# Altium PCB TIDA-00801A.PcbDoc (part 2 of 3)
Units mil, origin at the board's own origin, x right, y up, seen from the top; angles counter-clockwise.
Board outline 5000 x 3000 mil, 6 copper layers (Top Layer, Signal Layer 1, Signal Layer 2, Signal Layer 3, Signal Layer 4, Bottom Layer), stack 60.502 mil thick; 195 components, 95 nets, 602 pads, 757 vias.
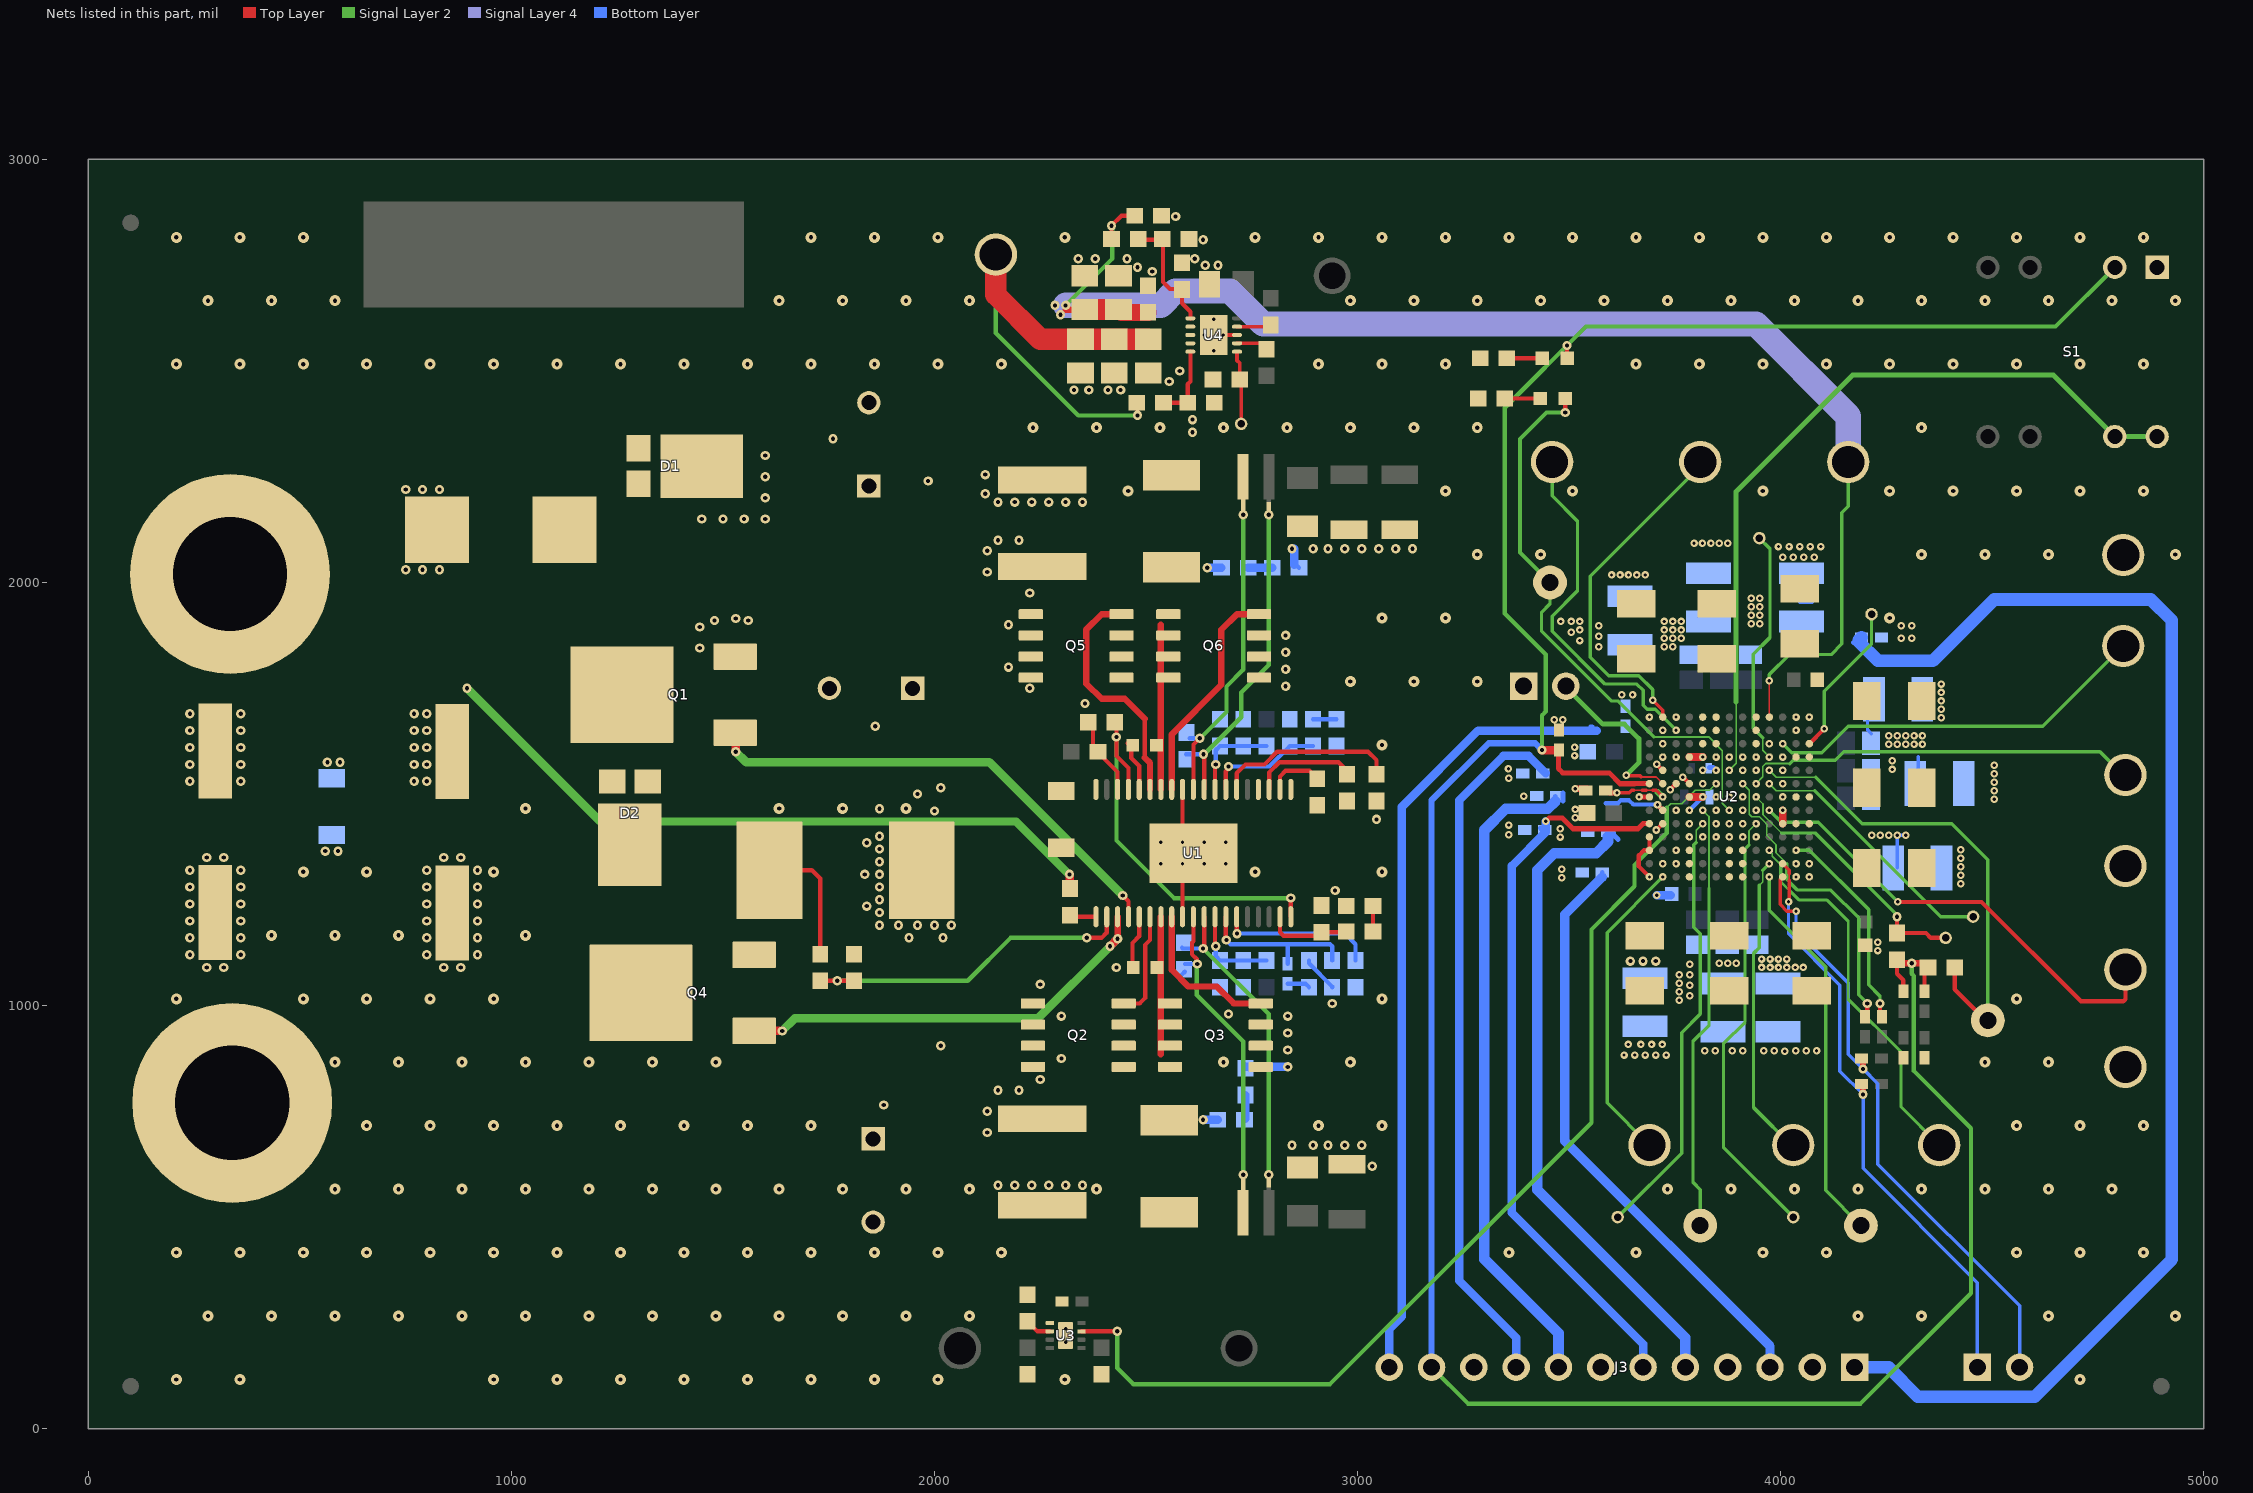
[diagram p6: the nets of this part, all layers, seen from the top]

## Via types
v1: diameter 22, hole 10, Top Layer to Bottom Layer, tented both sides, 258 vias
v2: diameter 26, hole 10, Top Layer to Bottom Layer, tented both sides, 214 vias
v3: diameter 17.72, hole 8, Top Layer to Bottom Layer, tented both sides, 162 vias
v4: diameter 17.7, hole 7.8, Top Layer to Bottom Layer, 104 vias
v5: diameter 19.68, hole 7.87, Top Layer to Bottom Layer, 14 vias
v6: diameter 18, hole 8, Top Layer to Bottom Layer, tented both sides, 5 vias

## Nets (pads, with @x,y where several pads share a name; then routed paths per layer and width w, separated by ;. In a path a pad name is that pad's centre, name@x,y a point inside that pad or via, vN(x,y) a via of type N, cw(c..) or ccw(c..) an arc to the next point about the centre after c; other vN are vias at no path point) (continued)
COMPA: C29.1 C32.1 U1.13 | length 391.6
  Top Layer w10: U1.13@2688.77,1210 2688.77,1156.23 v1(2690,1155)
  Bottom Layer w10: v1(2690,1155) 2700,1145 2820,1145 2935,1145 2940,1140 C32.1@2940,1106.5 ; C29.1@2835,1098.62 2835,1145
COMPB: C30.1 C33.1 U1.26 | length 276.7
  Top Layer w10: U1.26@2688.77,1511 2688.77,1553.77 2695,1560 v1(2695,1565)
  Bottom Layer w10: v1(2695,1565) 2791.5,1565 C33.1@2840,1613.5 C30.1@2895,1613.5
COMPC: C31.1 C34.1 U1.18 | length 197.5
  Top Layer w10: U1.18@2816.73,1210 2816.73,1173.27 2825,1165 C34.1@2915,1165 ; C34.1@2915,1173.5 2972.01,1173.5 C31.1@2973.5,1175
DS: C13.1 R4.2 U1.2 | length 817.1
  Top Layer w10: R4.2@1720,1058.5 C13.1@1810,1058.5 ; v1(2360,1160) 2395,1160 2407.27,1172.27 U1.2@2407.27,1210
  Signal Layer 2 w10: v1@1760,1058.5 2078.5,1058.5 2180,1160 v1@2355,1160
  other v1: 1770,1058.5
ENABLE1: TP9.1 U2.J5 | length 1031.7
  Signal Layer 2 w4: 3925.42,1380.42 3925.42,1413.44 v4(3941.99,1430)
  Signal Layer 2 w8: 3925.42,1380.42 3916,1371 3916,961 3865,910 3865,665 4027.5,502.5 TP9.1@4027.5,497.5
FBA: C12.1 R3.1 R5.2 U1.12 | length 218.4
  Top Layer w10: U1.12@2663.18,1210 2663.18,1141.82 v1(2665,1140)
  Bottom Layer w10: v1(2665,1140) 2665,1116.5 C12.1@2675,1106.5 R3.1@2785,1106.5
FBB: C27.1 R10.1 R11.2 U1.27 | length 217.4
  Top Layer w10: U1.27@2663.18,1511 2663.18,1568.18 v1(2665,1570)
  Bottom Layer w10: v1(2665,1570) 2665,1603.5 C27.1@2675,1613.5 R10.1@2785,1613.5
GA1: Q2.4 U1.6 | length 265.2
  Top Layer w10: Q2.4@2435,1005 2485,1005 2498,1018 2498,1143 2509.64,1154.64 U1.6@2509.64,1210
GA2: Q3.4 U1.8 | length 356.8
  Top Layer w15: U1.8@2560.82,1210 2560.82,1084.18 2600,1045 2667,1045 2707,1005 Q3.4@2759,1005
GB1: Q5.4 U1.33 | length 560.6
  Top Layer w10: 2497,1586 2497,1678
  Top Layer w15: Q5.4@2430,1930 2425,1925 2395,1925 2359,1889 2359,1761 2395,1725 2450,1725 2497,1678 ; 2497,1586 2509.64,1573.36 U1.33@2509.64,1511
GB2: Q6.4 U1.31 | length 519.9
  Top Layer w15: U1.31@2560.82,1511 2560.82,1640.82 2678,1758 2678,1888 2715,1925 2750,1925 Q6.4@2755,1930
GC1: Q4.1 U1.3 | length 1026.7
  Top Layer w10: Q4.1@1573.86,940.24 Q4.1@1574.09,940
  Top Layer w15: v1(2432.86,1157.86) U1.3@2432.86,1210
  Top Layer w20: Q4.1@1574.09,940 v1(1640,940) ; v1(2415,1140) v1(2432.86,1157.86)
  Signal Layer 2 w20: v1(1640,940) 1670,970 2245,970 v1(2415,1140) v1(2432.86,1157.86)
GC2: Q1.1 U1.4 | length 1157.1
  Top Layer w10: Q1.1@1528.86,1670.24 Q1.1@1530,1669.09 ; v1(2445,1260) 2458.45,1246.55 U1.4@2458.45,1210
  Top Layer w20: v1(1530,1600) Q1.1@1530,1644.09
  Signal Layer 2 w20: v1(1530,1600) 1555,1575 2130,1575 v1(2445,1260)
GND: C1.2 C2.2 C3.2 C4.2 C5.2 C6.2 C7.2 C8.2 C9.2 C10.2 C11.2 C12.2 C13.2 C15.1 C16.1 C17.2 C19.2 C20.2 C21.2 C22.1 C23.2 C24.2 C25.2 C27.2 C32.2 C33.2 C34.2 C35.1 C36.1 C37.2 C38.1 C39.2 C40.2 C41.2 C42.2 C43.2 C44.1 C45.2 C46.2 C47.1 C48.2 C49.1 C50.2 C51.1 C52.2 C53.1 C54.1 C55.1 C56.2 C57.2 C58.2 C59.2 C60.2 C61.2 C62.2 C63.2 C64.2 C65.1 C66.1 C67.1 C68.1 C69.2 C70.2 C71.2 C72.2 C73.2 C74.1 C75.2 C76.2 C77.2 C78.2 C79.1 C80.1 C81.1 C82.2 C83.2 J2.1 J3.2 J3.4 J3.7 J3.10 J5.1 Q3.1 Q3.2 Q3.3 Q6.1 Q6.2 Q6.3 R5.1 R6.1 R7.1 R11.1 R13.1 R14.1 R15.1 R23.1 R24.1 R30.2 R31.1 R32.1 S1.1 TP19.1 TP21.1 TP23.1 TP25.1 TP27.1 U1.9 U1.20 U1.23 U1.30 U1.36 U1.39 U2.A1 U2.A3 U2.A4 U2.A7 U2.A13 U2.B2 U2.B10 U2.B11 U2.B12 U2.C2 U2.C3 U2.C10 U2.C12 U2.C13 U2.D4 U2.D5 U2.D6 U2.D7 U2.D8 U2.D10 U2.E4 U2.E7 U2.E8 U2.E9 U2.E10 U2.F4 U2.F5 U2.F6 U2.F7 U2.F9 U2.F10 U2.G4 U2.G5 U2.G7 U2.G10 U2.H4 U2.H5 U2.H6 U2.H7 U2.H9 U2.H10 U2.J4 U2.J6 U2.J9 U2.J10 U2.K3 U2.L5 U2.L6 U2.L7 U2.L8 U2.L9 U2.L10 U2.M1 U2.M2 U2.M12 U2.M13 U2.N1 U2.N2 U2.N13 U3.5 U3.9 U4.4 U4.8 U4.11 | length 3222
  Top Layer w10: R6.1@1951.5,1363.5 R6.1@1960,1355 ; C17.2@2363.5,1670 2365,1670 2375,1660 2375,1611.5 C16.1@2386.5,1600 ; C16.1@2386.5,1605 C16.1@2386.5,1600 ; U1.36@2432.86,1511 2432.86,1552.14 2386.5,1598.5 C16.1@2386.5,1600 ; U1.9@2586.41,1210 v5(2586.41,1334.91) U1.39@2612,1360.5 v5(2586.41,1386.09) U1.30@2586.41,1511 ; U4.11@2660,2585 v5(2682.64,2585) U4.8@2715.12,2585 ; v4(3690.02,1304.02) 3665,1329.04 3665,1355 3677.01,1367.01 U2.A3@3690.02,1367.01 U2.A4@3690.02,1398.5 ; v6@3769.52,1539.49 U2.D8@3784.51,1524.49
  Top Layer w12: v3(3665.43,1492.99) U2.A7@3690.02,1492.99
  Top Layer w16: v3(3514.84,1512.68) C45.2@3542.4,1512.68
  Top Layer w18: U2.D7@3784.51,1492.99 v4(3816.01,1492.99) ; U2.D10@3784.51,1587.48 v4(3816.01,1587.48) ; U2.L5@4004.98,1430 v4(4004.98,1461.5)
  Signal Layer 2 w4: v4@3976,1363 3980,1359 3980,1353 4000,1333
  Signal Layer 2 w7: 4000,1293 4043,1250 4109,1250 4160,1199 4160,1015 4285,890 4285,760 TP23.1@4375,670
  Signal Layer 2 w8: TP19.1@3460,2285 3460,2205 3520,2145 3520,1980 3460,1920 3460,1885 3585,1760 3660,1760 3675,1745 3675,1710.19 3685.19,1700 3703.49,1700 v4(3753.02,1650.47) ; 4000,1293 4000,1333
  Bottom Layer w8: 4045.43,1952.83 4075.43,1952.83 ; C66.1@4205.43,1712.83 4205.43,1651.83 C65.1@4214.43,1642.83 ; C54.1@4275.43,1325.59 v3(4275.43,1402.83) v3(4295.43,1402.83) ; C68.1@4325.43,1527.83 4325.43,1587.83
  Bottom Layer w10: C11.2@2735,851.5 C11.2@2738.5,855 ; C23.2@2855,2041.5 C23.2@2861.5,2035 ; R13.1@2885,1106.5 2885,1100 2940,1045 C32.2@2940,1043.5 ; v4(3784.51,1461.5) v4(3816.01,1492.99)
  Bottom Layer w12: C36.1@3832.08,1562.83 3840.66,1562.83 v4(3847.5,1555.98)
  Bottom Layer w20: C11.2@2738.5,855 v1(2835,855) ; C23.2@2850,2041.5 v1@2850,2080 ; v3(3707.43,1260.83) C41.2@3739.92,1260.83
  other v1: 2150,575.4 2190,575.4 2230,575.4 2270,575.4 2310,575.4 2350,575.4 3035,620 2845,670 2895,670 2930,670 2970,670 3010,670 2835,895 2835,935 2835,975 2695,980 2940,1005 280,1090 320,1090 840,1090 880,1090 2430,1090 3645,1105 3675,1105 3705,1105 240,1120 360,1120 800,1120 920,1120 240,1160 360,1160 800,1160 920,1160 1940,1160 2020,1160 1870,1190 1915,1190 1960,1190 2000,1190 2040,1190 240,1200 360,1200 800,1200 920,1200 1870,1220 1840,1235 240,1240 360,1240 800,1240 920,1240 1870,1250 2947,1272 240,1280 360,1280 800,1280 920,1280 1870,1280 1835,1310 1870,1310 240,1320 360,1320 800,1320 920,1320 1870,1340 280,1350 320,1350 840,1350 880,1350 560,1365 590,1365 1870,1370 1840,1385 1870,1400 3045,1440 2000,1460 1870,1465 1960,1500 2356,1714 2830,1755 2830,1795 2830,1835 2830,1875 2845,2080 2895,2080 2930,2080 2970,2080 3010,2080 3050,2080 3090,2080 3130,2080 2150,2190 2190,2190 2230,2190 2270,2190 2310,2190 2350,2190 2120,2210 2120,2255 2610,2355 2610,2385 2330,2455 2365,2455 2410,2455 2440,2455 2555,2475 2580,2500 2515,2735 2480,2745 2640,2750 2670,2750 2340,2765 2380,2765 2455,2765 2615,2765 2635,2810 2570,2865
  other v2: 208,116 358,116 958,116 1108,116 1258,116 1408,116 1558,116 1708,116 1858,116 2008,116 2308,116 4708,116 283,266 433,266 583,266 733,266 883,266 1033,266 1183,266 1333,266 1483,266 1633,266 1783,266 1933,266 2083,266 4183,266 4333,266 4633,266 4933,266 208,416 358,416 508,416 658,416 808,416 958,416 1108,416 1258,416 1408,416 1558,416 1708,416 1858,416 2008,416 2158,416 3358,416 3658,416 3958,416 4108,416 4558,416 4708,416 4858,416 583,566 733,566 883,566 1033,566 1183,566 1333,566 1483,566 1633,566 1783,566 1933,566 2083,566 2383,566 3733,566 3883,566 4033,566 4183,566 4333,566 4483,566 4633,566 4783,566 658,716 808,716 958,716 1108,716 1258,716 1408,716 1558,716 1708,716 2908,716 3058,716 4558,716 4708,716 4858,716 583,866 733,866 883,866 1033,866 1183,866 1333,866 1483,866 2683,866 2983,866 4483,866 4633,866 208,1016 508,1016 658,1016 808,1016 958,1016 3058,1016 4558,1016 433,1166 583,1166 733,1166 1033,1166 508,1316 658,1316 958,1316 2758,1316 3058,1316 1033,1466 1633,1466 1783,1466 1933,1466 3058,1616 2983,1766 3133,1766 3283,1766 3058,1916 3208,1916 4258,1916 3283,2066 3433,2066 4333,2066 4483,2066 4633,2066 4933,2066 2458,2216 3208,2216 3508,2216 3958,2216 4258,2216 4408,2216 4558,2216 4708,2216 4858,2216 2233,2366 2383,2366 2533,2366 2683,2366 2833,2366 2983,2366 3133,2366 3283,2366 4333,2366 208,2516 358,2516 508,2516 658,2516 808,2516 958,2516 1108,2516 1258,2516 1408,2516 1558,2516 1708,2516 1858,2516 2008,2516 2158,2516 2908,2516 3058,2516 3208,2516 3658,2516 3808,2516 3958,2516 4108,2516 4258,2516 4408,2516 4558,2516 4708,2516 4858,2516 283,2666 433,2666 583,2666 1633,2666 1783,2666 1933,2666 2083,2666 2983,2666 3133,2666 3283,2666 3433,2666 3583,2666 3733,2666 3883,2666 4033,2666 4183,2666 4333,2666 4483,2666 4633,2666 4783,2666 4933,2666 208,2816 358,2816 508,2816 1708,2816 1858,2816 2008,2816 2308,2816 2758,2816 2908,2816 3058,2816 3208,2816 3358,2816 3508,2816 3658,2816 3808,2816 3958,2816 4108,2816 4258,2816 4408,2816 4558,2816 4708,2816 4858,2816
  other v3: 3760.43,1012.83 3785.43,1022.83 3760.43,1032.83 3785.43,1047.83 3760.43,1052.83 3760.43,1072.83 3785.43,1072.83 3955,1090 3975,1090 3995,1090 4015,1090 4035,1090 4054,1090 3785.43,1097.83 3855,1100 3875,1100 3895,1100 3955,1110 3975,1110 3995,1110 4015,1110 4230,1130 4230,1150 3482.36,1302.08 3482.36,1321.77 3479.36,1398.35 4215.43,1402.83 4235.43,1402.83 4255.43,1402.83 3357.36,1403.93 3479.36,1418.04 3357.36,1426.65 3514.84,1443.78 3514.84,1463.46 3393.12,1494.42 3357.36,1537.52 4264,1558 3356.8,1559.89 4264,1579 3513,1591 3513,1611 4255.43,1617.83 4275.43,1617.83 4295.43,1617.83 4315.43,1617.83 4335.43,1617.83 4255.43,1637.83 4275.43,1637.83 4295.43,1637.83 4315.43,1637.83 4335.43,1637.83 3465,1675.62 3485,1675.62 3625,1735 3650,1735 3570.43,1847.83 3725,1848 3745.43,1847.83 3525.43,1862.83 3725.43,1867.83 3745.43,1867.83 3765.43,1867.83 4285.43,1867.83 4310.43,1867.83 3570.43,1872.83 3505.43,1882.83 3525.43,1887.83 3725.43,1887.83 3745.43,1887.83 3765.43,1887.83 3570.43,1897.83 4285.43,1897.83 4310.43,1897.83 3930.43,1902.83 3950.43,1902.83 3480.43,1907.83 3505.43,1907.83 3525.43,1907.83 3725.43,1907.83 3745.43,1907.83 3765.43,1907.83 3930.43,1922.83 3950.43,1922.83 3930.43,1942.83 3950.43,1942.83 3930.43,1962.83 3950.43,1962.83
  other v4: 4036.48,1304.02 4067.98,1304.02 3721.52,1335.51 3753.02,1335.51 4036.48,1335.51 4067.98,1335.51 3753.02,1367.01 3973.49,1367.01 3784.51,1398.5 3816.01,1398.5 3847.5,1398.5 3879,1398.5 3910.5,1398.5 3941.99,1398.5 3784.51,1430 3847.5,1430 3879,1430 3910.5,1430 3847.5,1461.5 3910.5,1461.5 3941.99,1461.5 3847.5,1492.99 3879,1492.99 3910.5,1492.99 4004.98,1492.99 3816.01,1524.49 4004.98,1524.49 3816.01,1555.98 3910.5,1555.98 3941.99,1555.98 4004.98,1555.98 3721.52,1587.48 3753.02,1587.48 3847.5,1587.48 3879,1587.48 3910.5,1587.48 3941.99,1587.48 4004.98,1587.48 3721.52,1618.98 3721.52,1650.47 4036.48,1650.47 3690.02,1681.97 3753.02,1681.97 4036.48,1681.97 4067.98,1681.97
  other v5: 2310,204.25 2310,235.75 2535.23,1334.91 2637.59,1334.91 2688.77,1334.91 2535.23,1386.09 2637.59,1386.09 2688.77,1386.09 2660,2547.6 2637.36,2585 2660,2622.4
  other v6: 3769,1540
GPIO_4: TP14.1 U2.K10 | length 560.4
  Signal Layer 2 w4: 3957.66,1632.66 3957.66,1603.31 v4(3973.49,1587.48)
  Signal Layer 2 w8: TP14.1@3950,2105 3975,2080 3975,1932.84 3975,1870 3935,1830 3935,1655.33 3957.66,1632.66
GPIO_6: TP15.1 U2.N11 | length 363.5
  Top Layer w10: U2.N11@4067.98,1618.98 v3@4102.94,1653.94
  Signal Layer 2 w8: v3(4102.94,1654.41) 4102.93,1742.93 4215,1855 TP15.1@4215,1922
GPIO_7: S1.2 S1.4 U2.G9 | length 1839.8
  Signal Layer 2 w4: v4(3879,1555.98) 3895.42,1572.41 3895.42,1718.08
  Signal Layer 2 w12: 3895,1718.08 3895,2215 4170,2490 4645,2490 S1.4@4790,2345 S1.2@4895,2345
INT: TP6.1 U2.K1 | length 913.7
  Signal Layer 2 w8: v4(3973.49,1304.02) 3973.49,1224.77 4107,1091.26 4107,563 TP6.1@4190,480
LDO1: C57.1 J3.5 U2.C6 | length 1559.8
  Bottom Layer w12: C57.1@3600.43,1407.83 3615.43,1392.83
  Bottom Layer w20: C57.1@3591.98,1399.38 C57.1@3600.43,1407.83
  Bottom Layer w25: C57.1@3591.98,1399.38 3591.98,1387.7 3564.29,1360 3465,1360 3425,1320 3425,565 3775,215 J3.5@3775,145
  other v4: 3753.02,1461.5
LDO2: C58.1 J3.8 U2.B6 | length 1720.3
  Top Layer w10: v6@3706.53,1476.49 U2.B6@3721.52,1461.5
  Bottom Layer w10: 3467.24,1482.24 C58.1@3467.24,1495 ; 3587,1478 3615,1478 3622,1485 3642,1485 3652,1475 v6(3709,1475)
  Bottom Layer w12: 3485.31,1483.15 C58.1@3485.31,1502.83
  Bottom Layer w25: 3467.24,1482.24 3450,1465 3350,1465 3300,1415 3300,400 3475,225 J3.8@3475,145
LDO3: C60.1 J3.1 U2.K11 | length 3310.1
  Bottom Layer w12: 4172.43,1857.83 4186.43,1871.83 C60.1@4193.43,1871.83 ; C60.1@4185.43,1859.83 C60.1@4185.43,1862.83
  Bottom Layer w30: J3.1@4170,145 4255,145 4325,75 4600,75 4925,400 4925,1910 4875,1960 4505,1960 4360,1815 4230,1815 4185.43,1859.57 4185.43,1864.06 C60.1@4191.38,1870
  other v4: 3973.49,1618.98
LDO9: C64.1 J3.6 U2.A5 | length 1744
  Top Layer w12: v3(3445,1435.5) 3452.33,1442.83 3484.43,1442.83 3509.43,1417.83 3662.83,1417.83 3675,1430 U2.A5@3690.02,1430
  Bottom Layer w12: C64.1@3440.92,1410.92 3432.55,1419.29 3441.41,1419.29 C64.1@3446.92,1413.78
  Bottom Layer w20: v3(3445,1435.5) 3445,1410 3365,1330 3365,510 3675,200 J3.6@3675,145
LDOLN: C59.1 J3.3 U2.B5 | length 1433.8
  Top Layer w10: v6(3706.53,1415) U2.B5@3721.52,1430
  Bottom Layer w10: C59.1@3578.62,1303.62 C59.1@3578.62,1315
  Bottom Layer w22: C59.1@3578.62,1303.62 3490,1215 3490,680 3975,195 3975,148 J3.3@3975,140
LDOUSB: C61.1 J3.12 U2.B9 | length 1899
  Top Layer w10: v6@3705.53,1571.98 U2.B9@3721.52,1555.98
  Bottom Layer w10: 3550.62,1659.38 3555,1659.38
  Bottom Layer w20: J3.12@3075,145 3075,235 3105,265 3105,1470 3285,1650 3565,1650
  other v6: 3707.51,1570
LDOVANA: C63.1 J3.9 U2.C8 | length 1683.1
  Top Layer w10: v6@3738.03,1509.49 U2.C8@3753.02,1524.49
  Bottom Layer w20: J3.9@3375,145 3375,215 3240,350 3240,1485 3345,1590 3404.28,1590 C63.1@3445.43,1548.85
  other v6: 3739,1510
LDOVRTC: C62.1 D3.1 J3.11 R20.1 R21.2 R22.2 R25.2 S1.3 U2.A8 | length 6925.3
  Top Layer w8: R25.2@4275,1108.5 R25.2@4283.5,1100
  Top Layer w10: v1(3495,2560) 3495,2531.02 D3.1@3496.02,2530 ; R25.2@4275,1108.5 4275,1075 4290,1060 R22.2@4290,1033.62 ; R21.2@4340,1033.62 4340,1086.5 4348.5,1095 R20.1@4343.5,1100
  Top Layer w12: C62.1@3475,1600 3475,1560 3485,1550 3595,1550 3620.69,1524.31 3654.88,1524.31 3654.88,1524.49 U2.A8@3690.02,1524.49
  Top Layer w15: R25.2@4283.5,1100 v1(4310,1100) R20.1@4343.5,1100
  Top Layer w20: v1(3436,1604) C62.1@3476,1604
  Signal Layer 2 w10: J3.11@3175,145 3261,59 4189,59 4450,320 4450,710 4315,845 4315,1070 4310,1075 v1(4310,1100) ; v1(3436,1604) 3436,1686 3445,1695 3445,1830 3348,1927 3348,2413 3540,2605 4650,2605 S1.3@4795,2750
  Bottom Layer w15: J3.11@3175,145 3175,1485 3310,1620 3420,1620 v1(3436,1604)
NetC11_1: C11.1 R2.1 | length 59.3
  Bottom Layer w10: R2.1@2732.99,730 R2.1@2735,732.01
  Bottom Layer w20: R2.1@2735,732.01 C11.1@2735,788.5
NetC14_2: C14.2 U1.5 | length 126.6
  Top Layer w10: C14.2@2468,1090 2468,1148 2484.05,1164.05 U1.5@2484.05,1210
NetC22_2: C22.2 U1.21 | length 132.2
  Top Layer w10: U1.21@2816.73,1511 2816.73,1541.73 2830,1555 2886.5,1555 C22.2@2905,1536.5
NetC23_1: C23.1 R9.1 | length 57
  Bottom Layer w20: R9.1@2741.5,2035 C23.1@2798.5,2035
NetC24_1: C24.1 U1.14 | length 368.9
  Top Layer w10: v1@2714.36,1170 U1.14@2714.36,1210
  Bottom Layer w10: v1(2715,1170) 2970,1170 2995,1145 C24.1@2995,1106.5
NetC25_1: C25.1 U1.25 | length 431.8
  Top Layer w10: U1.25@2714.36,1511 2714.36,1549.36 2735,1570 2780,1570 2810,1600 3025,1600 3045,1580 C25.1@3045,1546.5
NetC26_2: C26.2 U1.34 | length 120.2
  Top Layer w10: C26.2@2457,1620 2465,1612 2465,1585 2484.05,1565.95 U1.34@2484.05,1511
NetC29_2: C29.2 R13.2 | length 53.3
  Bottom Layer w10: C29.2@2835,1051.38 2877.13,1051.38 R13.2@2885,1043.5
NetC30_2: C30.2 R14.2 | length 55
  Bottom Layer w10: C30.2@2895,1676.5 R14.2@2950,1676.5
NetC31_2: C31.2 R15.2 | length 60
  Top Layer w10: C31.2@3036.5,1175 R15.2@3036.5,1235
NetC45_1: C45.1 U2.B7 | length 165.7
  Top Layer w4: 3652.63,1508.74 3672.32,1508.74 ; 3682.16,1508.74 3697.91,1508.74
  Top Layer w8: v3(3613.26,1502.83) 3641.84,1502.83 3647.75,1508.74 3652.63,1508.74 ; 3672.32,1508.74 3682.16,1508.74 ; 3697.91,1508.74 3705.78,1508.74 v4(3721.52,1492.99)
  Top Layer w12: C45.1@3585.7,1512.68 3595.55,1502.83 v3(3613.26,1502.83)
  Signal Layer 2 w10: 3710,1504.51 3710,1505
  Signal Layer 2 w15: 3710,1504.51 v4(3721.52,1492.99)
NetC71_1: C71.1 U3.6 | length 62.4
  Top Layer w10: C71.1@2220,253.5 2243.66,229.84 U3.6@2272.6,229.84
NetC77_1: C77.1 TP2.1 U4.6 | length 173.3
  Top Layer w9: U4.6@2715.12,2545.63 2715.12,2524.88 2721.5,2518.5 2721.5,2500 C77.1@2721.5,2480 ; TP2.1@2725,2375 C77.1@2725,2480
NetC78_1: C78.1 R28.1 U4.5 | length 180.3
  Top Layer w10: R28.1@2541.5,2425 C78.1@2598.5,2425 2598.5,2468.5 2604.88,2474.88 U4.5@2604.88,2545.63
NetC80_2: C80.2 R29.2 R30.1 U4.1 | length 286.2
  Top Layer w10: R29.2@2481.5,2810 R30.1@2538.5,2810 ; R30.1@2540,2810 2540,2710 2556.5,2693.5 2585,2693.5 2585,2660 2604.88,2640.12 U4.1@2604.88,2624.37
NetD1_1: D1.1 D1.2 D2.1 D2.2 L1.2 Q1.4
NetD2_3: D2.3 Q4.4
NetD3_2: D3.2 R31.2 | length 84
  Top Layer w10: R31.2@3352.99,2530 D3.2@3436.97,2530
NetD4_2: D4.2 R32.2 | length 84
  Top Layer w10: R32.2@3347.99,2435 D4.2@3431.97,2435
NetJ4_1: J4.1 R17.1 U2.L2 | length 1409.3
  Top Layer w4: 4020.74,1296.14 4020.74,1311.89
  Top Layer w8: U2.L2@4004.98,1335.51 4020.74,1319.76 4020.74,1311.89 ; v3(4018.77,1244.96) 4020.74,1246.93 4020.74,1296.14
  Top Layer w15: R17.1@4191.38,815 4195,811.38 v1(4195,790)
  Bottom Layer w8: v3(4018.77,1244.96) 4018.77,1226.58 4018.63,1226.44 4018.63,1199.46 4018.77,1199.32 4018.77,1169.49 4140,1048.26 4140,845 v1(4195,790) 4195,615 4465,345 J4.1@4465,145
NetJ4_2: J4.2 R16.1 U2.L1 | length 1435
  Top Layer w8: U2.L1@4004.98,1304.02 3999.09,1298.11 3999.09,1239.05 4014.84,1223.3 v3(4036.49,1223.3)
  Top Layer w15: R16.1@4191.38,875 4195,871.38 v1(4195,850)
  Bottom Layer w8: v3(4036.49,1223.3) 4036.49,1176.77 4160,1053.26 4160,885 v1(4195,850) 4230,815 4230,625 4565,290 J4.2@4565,145
NetJ5_2: J5.2 U2.B8 | length 421.6
  Top Layer w4: 3670.91,1540.23 3705.78,1540.23 U2.B8@3721.52,1524.49
  Top Layer w8: v3@3634.92,1542.98 3668.16,1542.98 3670.91,1540.23
  Signal Layer 2 w11.81: J5.2@3495.83,1759.17 3495.83,1749.17 3580,1665 3630.81,1665 3665,1630.81 3665,1574.27 v3(3634.92,1544.17)
NetL2_2: L2.2 NT1.2 R1.1
NetL3_2: L3.2 NT3.2 R8.1
NetL4_1: L4.1 U2.E11 U2.E12 U2.E13
NetL5_1: L5.1 U2.F11 U2.F12 U2.F13
NetL6_1: L6.1 U2.J11 U2.J12 U2.J13
NetL7_1: L7.1 U2.G1 U2.G2 U2.G3
NetL8_1: L8.1 U2.H1 U2.H2 U2.H3
NetL9_1: L9.1 U2.M5 U2.N5
NetL10_1: L10.1 U2.D1 U2.D2 U2.D3
NetL11_1: L11.1 U2.M10 U2.N10
NetL12_1: L12.1 U2.M7 U2.N7
NetQ4_3: Q4.3 R4.1 R6.2 | length 310.9
  Top Layer w10: R6.2@1610,1320 1710,1320 1730,1300 1730,1131.5 R4.1@1720,1121.5
NetR7_2: R7.2 U1.22 | length 242.2
  Top Layer w10: U1.22@2791.14,1511 2791.14,1551.14 2815,1575 2955,1575 R7.2@2975,1555
NetR12_2: R12.2 U1.1 | length 65.2
  Top Layer w10: R12.2@2316.5,1210 U1.1@2381.68,1210
NetR18_1: R18.1 U2.H8 | length 727.6
  Top Layer w10: R18.1@4205,973.62 v1(4205,1005)
  Signal Layer 2 w4: v4(3910.5,1524.49) 3926,1509 3926,1452 3932,1446 3950,1446 3967,1429 3967,1402 3989,1380 3989,1361 4015,1335
  Signal Layer 2 w8: 4015,1335 4015,1298 4040,1273 4119,1273 4185,1207 4185,1025 4200,1010 v1@4200,1005
NetR19_1: R19.1 U2.M3 | length 494.1
  Top Layer w10: R19.1@4235,973.62 v1(4235,1005)
  Signal Layer 2 w8: v4(4036.48,1367.01) 4067.99,1367.01 4208,1227 4208,1049 4235,1022 v1(4235,1005)
NetR25_1: R25.1 TP13.1 U2.J7 | length 627.9
  Top Layer w10: R25.1@4275,1168.24 R25.1@4275,1171.5 ; v1(4275,1210) R25.1@4275,1171.5 ; TP13.1@4390,1160 4355,1160 4343.5,1171.5 R25.1@4275,1171.5
  Signal Layer 2 w4: v4(3941.99,1492.99) 3958.63,1476.36 3958.63,1451.37 4002.16,1407.84
  Signal Layer 2 w8: 4002.16,1407.84 4082.16,1407.84 v1@4277.5,1212.5
NetR26_1: R26.1 U4.7 | length 75.6
  Top Layer w9: U4.7@2715.12,2565.31 2771.18,2565.31 R26.1@2785,2551.5
NetR27_1: R27.1 U4.9 | length 81.5
  Top Layer w9: U4.9@2715.12,2604.69 2791.18,2604.69 R27.1@2795,2608.5
NRESWARM: TP8.1 U2.E6 | length 1005.4
  Signal Layer 2 w4: v4(3816.01,1461.5) 3830.87,1446.64 3830.87,1277.39
  Signal Layer 2 w8: TP8.1@3810,485 3810,565 3793,582 3793,915.42 3830.87,953.29 3830.87,1277.39
NSLEEP: TP10.1 U2.E5 | length 1027.4
  Signal Layer 2 w4: 3800.42,1385.42 3800.42,1414.42 v4(3816.01,1430)
  Signal Layer 2 w8: TP10.1@3617.5,497.5 3617.5,502.5 3766,651 3766,936 3810,980 3810,1170 3794.76,1185.24 3794.76,1372.18 3794.76,1379.76 3800.42,1385.42
PHA: C14.1 L2.1 Q2.1 Q2.2 Q2.3 Q3.5 Q3.6 Q3.7 Q3.8 R2.2 U1.7 | length 360
  Top Layer w15: 2535.23,885 2535.23,1090 U1.7@2535.23,1210
  Bottom Layer w20: v1(2635,730) R2.2@2670,730
PHB: C26.1 L3.1 Q5.1 Q5.2 Q5.3 Q6.5 Q6.6 Q6.7 Q6.8 R9.2 U1.32 | length 422.5
  Top Layer w15: U1.32@2535.23,1511 2535.23,1900
  Bottom Layer w20: v1(2645,2035) R9.2@2678.5,2035
PWRDOWN: TP7.1 U2.K8 | length 603.8
  Signal Layer 2 w4: v4(3973.49,1524.49) 3990.13,1507.86 4011.14,1507.86 4080.42,1507.84
  Signal Layer 2 w8: 4080.42,1507.84 4378.26,1210 4440,1210 TP7.1@4445,1205
REGEN1: U2.F8 U3.3 | length 2525.4
  Top Layer w10: U3.3@2347.4,229.84 2431.84,229.84 v1(2432,230)
  Signal Layer 2 w4: 3731,1468 3740,1477 3766,1477 3798,1509 3832,1509 3848,1525 3847,1525 v4(3847.5,1524.49)
  Signal Layer 2 w10: v1(2432,230) 2432,143 2470,105 2935,105 3553,723 3553,1180 3655,1282 3655,1332 3731,1408 3731,1468
RESET_IN: R20.2 TP11.1 U2.K9 | length 1149.3
  Top Layer w10: R20.2@4411.5,1095 4411.5,1038.5 4485,965 TP11.1@4490,965
  Signal Layer 2 w4: v4(3973.49,1555.98) 3989.48,1540 4083,1540
  Signal Layer 2 w8: 4083,1540 4193,1430 4405,1430 4490,1345 TP11.1@4490,965
RESET_OUT: D4.1 TP12.1 U2.G6 | length 1351.6
  Top Layer w10: v1(3491.02,2402) D4.1@3491.02,2435
  Signal Layer 2 w4: 3700,1635 3830,1635 3862.36,1602.64 3862.36,1478.14 v4@3880,1460.5
  Signal Layer 2 w8: TP12.1@3455,2000 3455,1950 3435,1930 3435,1885 3600,1720 3615,1720 3700,1635
  Signal Layer 2 w10: TP12.1@3455,2000 3384,2071 3384,2339 3447,2402 v1(3491.02,2402)
  other v4: 3879,1461.5
SA1: C18.1 NT1.1 U1.10 | length 699.1
  Top Layer w10: U1.10@2612,1210 2612,1152 2609,1149 2609,1121 2620,1110 v1@2620,1098
  Signal Layer 2 w10: v1@2620,1098 2620,1025 2730,915 v1(2730,600)
  Bottom Layer w10: C18.1@2585,1073.5 C18.1@2591.5,1080 ; C18.1@2592.5,1098 v1(2621,1098)
SA2: C18.2 NT2.1 U1.11 | length 730
  Top Layer w10: v1(2635,1135) v1@2637.59,1132.41 ; v1@2637.59,1135 U1.11@2637.59,1210
  Signal Layer 2 w10: v1@2632.5,1132.5 2637.5,1132.5 2790,980 v1(2790,600)
  Bottom Layer w10: C18.2@2585,1136.5 2586.5,1135 v1(2635,1135)
SB1: C28.2 NT3.1 U1.29 | length 720.3
  Top Layer w10: U1.29@2612,1511 2612,1617 v1@2626,1631
  Signal Layer 2 w10: v1@2627.5,1631.5 2690,1694 2690,1754 2730,1794 v1(2730,2160)
  Bottom Layer w10: C28.2@2603.5,1632 v1(2627,1632)
SB2: C28.1 NT4.1 U1.28 | length 758.8
  Top Layer w10: v1@2635,1600 v1@2637.59,1597.41 ; U1.28@2637.59,1511 v1@2637.59,1594
  Signal Layer 2 w10: v1@2637.59,1594 2725,1681.41 2725,1740 2790,1805 v1(2790,2160)
  Bottom Layer w10: C28.1@2594.5,1594 2629,1594 v1@2635,1600
  other v1: 2636,1594
SMPS1_2: C39.1 C46.1 L4.2 L5.2 TP16.1 U2.B13 | length 823.6
  Top Layer w8: v3(3697.91,1721.34) 3721.53,1697.71 U2.B13@3721.52,1681.97
  Signal Layer 2 w8: v3(3697.91,1721.34) 3697.9,1747.1 3665,1780 3593.5,1780 3550,1823.5 3550,2015 3810,2275 TP16.1@3810,2285
  other v3: 3600.43,2017.83 3620.43,2017.83 3640.43,2017.83 3660.43,2017.83 3680.43,2017.83 3795.43,2092.83 3815.43,2092.83 3835.43,2092.83 3855.43,2092.83 3875.43,2092.83
SMPS3: C48.1 C79.2 C81.2 C82.1 C83.1 L6.2 R29.1 TP17.1 U2.K13 U4.2 | length 3366.6
  Top Layer w4: U2.K13@3973.49,1681.97 v3(3973.5,1767.83)
  Top Layer w10: R29.1@2418.5,2810 v1(2418.5,2843.5) 2442,2867 C79.2@2473.5,2867
  Top Layer w15: v1@2310,2645 C82.1@2355,2645
  Top Layer w35: C83.1@2435,2645 C83.1@2441.5,2638.5
  Top Layer w40: C83.1@2441.5,2638.5 C81.2@2505,2638.5
  Top Layer w50: C82.1@2355,2645 C83.1@2435,2645
  Signal Layer 2 w8: v3(3973.5,1767.83) 3973.49,1782.49 4020.67,1829.67 4119.67,1829.67 4145,1855 4145,2165 4160,2180 TP17.1@4160,2285
  Signal Layer 2 w10: v1(2310,2655) 2420,2765 2420,2845 v1(2418.5,2843.5)
  Signal Layer 4 w60: v1(2310,2655) 2535,2655 2569,2689 2699,2689 2777,2611 3942,2611 4160,2393 TP17.1@4160,2285
  other v1: 2298,2633 2285,2655
  other v3: 4005,2060 4030,2060 4055,2060 4080,2060 3995,2085 4020,2085 4045,2085 4070,2085 4095,2085
SMPS4_5: C50.1 C52.1 L7.2 L8.2 TP18.1 U2.K2 | length 725
  Signal Layer 2 w4: 3950,1284 3958,1292 3958,1320.03
  Signal Layer 2 w8: 3950,1284 3950,1137 3936,1123 3936,759 TP18.1@4030,665 ; 3958,1320.03 v4(3973.49,1335.51)
  other v3: 4010,892 3820.43,892.83 3845.43,892.83 3885.43,892.83 3910.43,892.83 3960.43,892.83 3985.43,892.83 4035.43,892.83 4060.43,892.83 4085,893
SMPS6: C54.2 L9.2 TP20.1 U2.K6 | length 1100.6
  Top Layer w10: v3(4277,1245) 4475,1245 4710,1010 4810,1010 4815,1015 TP20.1@4815,1085
  Signal Layer 2 w8: v4(3973.49,1461.5) 4002.15,1432.84 4089.16,1432.84 v3(4277,1245)
  other v3: 4425.43,1287.83 4425.43,1307.83 4425.43,1327.83 4425.43,1347.83 4425.43,1367.83
SMPS7: C56.1 L10.2 TP22.1 U2.B1 | length 729.9
  Signal Layer 2 w8: TP22.1@3690,670 3590,770 3590,1172.5 v4(3721.52,1304.02)
  other v3: 3630,883 3655,883 3680,883 3705,883 3730,883 3640,908 3670,908 3695,908 3720,908
SMPS8: C66.2 L11.2 TP24.1 U2.L11 | length 918.2
  Signal Layer 2 w8: v4(4004.98,1618.98) 4026.12,1597.84 4097.83,1597.84 4160.01,1660.01 4619.95,1659.97 TP24.1@4810,1850
  other v3: 4380,1680 4380,1700 4380,1720 4380,1740 4380,1760
SMPS9: C68.2 L12.2 TP26.1 U2.J8 | length 943.5
  Signal Layer 2 w4: v4(3941.99,1524.49) 3958,1540.51 3958,1565 3965,1572 4022,1572
  Signal Layer 2 w8: 4022,1572 4030,1580 4129,1580 4149,1600 4755,1600 TP26.1@4815,1540
  other v3: 4505.43,1487.83 4505.43,1507.83 4505.43,1527.83 4505.43,1547.83 4505.43,1567.83
VBAT: C2.1 C3.1 C4.1 J1.1 L1.1 R12.1 | length 1640.6
  Top Layer w10: v1(2319,1310) v1@2320,1309
  Top Layer w20: R12.1@2320,1276.5 v1@2320,1309
  Signal Layer 2 w20: v1(895,1750) 1210,1435 2193,1435 v1@2319,1309
  other v1: 240,1530 360,1530 770,1530 800,1530 240,1570 360,1570 770,1570 800,1570 565,1575 595,1575 240,1610 360,1610 770,1610 800,1610 240,1650 360,1650 770,1650 800,1650 240,1690 360,1690 770,1690 800,1690 750,2030 790,2030 830,2030 750,2220 790,2220 830,2220
VIN: C1.1 C5.1 C6.1 C7.1 C8.1 C15.2 D1.3 Q1.3 Q2.5 Q2.6 Q2.7 Q2.8 Q5.5 Q5.6 Q5.7 Q5.8 U1.38
  other v1: 2125,700 2125,750 1880,765 2150,800 2200,800 2250,825 2300,875 2015,905 2300,975 2250,1050 2015,1515 1860,1660 2225,1750 2175,1800 1445,1845 1445,1895 2175,1900 1480,1910 1560,1910 1530,1915 2225,1975 2125,2025 2125,2075 2150,2100 2200,2100 1450,2150 1500,2150 1550,2150 1600,2150 1600,2200 1985,2240 1600,2250 1600,2300 1760,2340
VREG: C17.1 U1.19 U1.35 | length 930.5
  Top Layer w10: C17.1@2426.5,1670 C17.1@2430,1673.5 ; C17.1@2435,1665 2430,1660 2430,1590 2458.45,1561.55 U1.35@2458.45,1511 ; U1.19@2842.32,1210 v1@2842.32,1254
  Signal Layer 2 w10: v1(2430,1635) 2430,1390 2566.14,1253.86 v1@2842.32,1253.86
  other v1: 2842,1254
VTT: C74.2 C75.1 C76.1 R28.2 TP1.1 U4.3 | length 1129.9
  Top Layer w10: R28.2@2478.5,2425 2480,2423.5 v1(2480,2395)
  Top Layer w50: TP1.1@2145,2775 2145,2680 2250,2575 C74.2@2505,2575
  Signal Layer 2 w10: TP1.1@2145,2775 2145,2590 2340,2395 v1(2480,2395)
pads on no net: FID1.1 FID2.1 FID3.1 FID4.1 FID5.1 FID6.1 H1.0 H2.0 H3.0 H4.0 Logo1.0 S1.5 S1.6 S1.7 S1.8 U1.15 U1.16 U1.17 U1.24 U2.A2 U2.A12 U2.B4 U2.C1 U2.C9 U2.C11 U2.G8 U2.K4 U2.K5 U2.K12 U2.L4 U2.M11 U2.N12

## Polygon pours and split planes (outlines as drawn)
GND on Bottom Layer "Top Layer-No Net" (solid, remove dead copper, pour order 249): 50,2950 4950,2950 4950,50 50,50
GND on Bottom Layer "BOTTOM-GND 14" (solid, pour order 240): 4175,1770 4260.43,1770 4260.43,1637.83 4260.43,1622.83 4200.43,1622.83 4170.43,1662.83 4170.43,1767.83
GND on Bottom Layer "BOTTOM-GND 13" (solid, pour order 248): 4070.43,1927.83 4050.43,1927.83 3955.43,1832.83 3955.43,1817.83 3715.43,1817.83 3705.43,1827.83 3545.43,1827.83 3468.86,1904.4 3468.4,1904.9 3467.98,1905.45 3467.61,1906.03 3467.3,1906.64 3467.04,1907.27 3466.83,1907.93 3466.68,1908.6 3466.59,1909.28 3466.56,1909.96 3466.59,1910.65 3466.68,1911.33 3466.83,1912 3467.04,1912.65 3467.3,1913.29 3467.62,1913.9 3467.99,1914.48 3468.41,1915.02 3468.87,1915.53 3469.38,1915.99 3469.93,1916.41 3470.5,1916.77 3471.11,1917.09 3471.75,1917.35 3472.4,1917.56 3473.07,1917.71 3473.75,1917.8 3474.43,1917.83 3720.43,1917.83 3729.31,1926.71 3756.55,1926.71 3756.55,1953.95 3775.43,1972.83 3945.43,1972.83 3955.43,1982.83 4070.43,1982.83 4070.43,1927.83
GND on Bottom Layer "BOTTOM-GND 11" (solid, pour order 247): 3770.43,1167.83 3985.43,1167.83 4070.43,1082.83 4070.43,1012.83 3795.43,1012.83 3780.43,997.83 3625.43,997.83 3625.43,1067.83 3725.43,1167.83
GND on Bottom Layer "BOTTOM-GND 10" (solid, pour order 241): 4305.43,1272.83 4220.43,1272.83 4205.43,1287.83 4205.43,1412.83 4300.43,1412.83 4305.43,1407.83 4305.43,1272.83
GND on Bottom Layer "BOTTOM-GND 9" (solid, pour order 244): 4355.43,1457.83 4200.43,1457.83 4200.43,1647.83 4355.43,1647.83 4355.43,1457.83
GND on Bottom Layer "BOTTOM-GND 7" (solid, pour order 229): 3540.43,1335.83 3473.43,1335.83 3473.43,1292.83 3490.43,1292.83 3500.43,1297.83 3540.43,1297.83 3540.43,1335.83
GND on Bottom Layer "BOTTOM-GND 5" (solid, pour order 224): 3617.5,1700 3617.5,1740 3652.5,1740 3652.5,1700 3617.5,1700
GND on Bottom Layer "BOTTOM-GND 3" (solid, pour order 230): 3550.43,1387.83 3470.43,1387.83 3470.43,1427.83 3550.43,1427.83 3550.43,1387.83
GND on Bottom Layer "BOTTOM-GND 2" (solid, pour order 225): 3350.43,1397.83 3390.43,1397.83 3395.43,1402.83 3395.43,1432.83 3350.43,1432.83 3350.43,1397.83
GND on Bottom Layer "BOTTOM-GND 1" (solid, pour order 227): 3350.43,1527.83 3390.43,1527.83 3395.43,1532.83 3395.43,1567.83 3350.43,1567.83 3350.43,1527.83
LDOVANA on Bottom Layer "BOTTOM-LDOVANA" (solid, pour order 238): 3720.43,1532.83 3745.43,1517.83 3745.43,1503.44 3744.55,1502.73 3743.74,1501.96 3742.99,1501.11 3742.32,1500.2 3741.91,1499.56 3741.24,1498.43 3732.63,1499.66 3732.14,1500.36 3731.46,1501.25 3730.7,1502.09 3729.88,1502.85 3728.98,1503.54 3728.04,1504.15 3727.04,1504.67 3726,1505.11 3724.92,1505.45 3723.82,1505.7 3722.71,1505.85 3721.58,1505.91 3720.46,1505.86 3719.34,1505.72 3718.24,1505.48 3717.16,1505.14 3716.12,1504.72 3715.12,1504.2 3714.16,1503.6 3713.41,1503.04 3712.74,1502.5 3710.43,1502.83 3673.8,1502.83 3672.92,1503.52 3671.97,1504.13 3670.97,1504.66 3669.93,1505.1 3668.86,1505.44 3667.76,1505.69 3666.65,1505.85 3665.52,1505.91 3664.39,1505.86 3663.28,1505.72 3662.17,1505.49 3661.1,1505.16 3660.05,1504.73 3659.05,1504.22 3658.09,1503.62 3657.33,1503.05 3627,1503.05 3626.76,1504.75 3626.55,1505.92 3626.23,1507.06 3625.81,1508.18 3625.3,1509.25 3624.69,1510.27 3624,1511.24 3623.22,1512.14 3622.37,1512.98 3621.45,1513.73 3620.47,1514.41 3619.44,1514.99 3618.35,1515.48 3617.23,1515.88 3616.08,1516.17 3614.9,1516.37 3613.72,1516.46 3612.53,1516.45 3611.34,1516.33 3610.17,1516.11 3609.03,1515.79 3607.91,1515.37 3606.91,1514.9 3605.94,1514.39 3595.55,1520.55 3525.98,1520.55 3525.26,1521.49 3524.45,1522.36 3523.57,1523.16 3522.62,1523.88 3521.61,1524.52 3520.56,1525.06 3519.46,1525.51 3518.32,1525.87 3517.16,1526.12 3515.98,1526.27 3514.79,1526.32 3513.6,1526.26 3512.42,1526.1 3511.26,1525.84 3510.12,1525.47 3509.03,1525.01 3507.97,1524.46 3506.97,1523.82 3506.03,1523.09 3505.16,1522.28 3504.36,1521.4 3503.7,1520.55 3477.44,1520.55 3480,1520.55 3450.61,1535.77 3431.19,1552.57 3430.19,1552.57 3430.19,1567.79 3435.43,1567.83 3470.44,1563.58 3614.9,1563.58 3615.43,1542.83 3622.08,1539.5 3622.37,1538.84 3622.88,1537.76 3624.18,1535.77 3624.95,1534.86 3625.8,1534.03 3626.72,1533.27 3627.7,1532.6 3628.73,1532.01 3629.82,1531.52 3630.94,1531.12 3632.09,1530.82 3633.26,1530.63 3634.45,1530.53 3635.64,1530.54 3636.82,1530.66 3637.99,1530.88 3639.14,1531.19 3640.26,1531.61 3641.33,1532.12 3642.35,1532.73
5V0 on Bottom Layer "BOTTOM-V_LDOUSB_IN2" (solid, pour order 226): 3600.43,1582.83 3645.43,1582.83 3645.43,1617.83 3600.43,1617.83 3600.43,1582.83
LDO1 on Bottom Layer "BOTTOM-LDO1" (solid, pour order 232): 3646.52,1447.33 3665.43,1457.83 3730.43,1457.83 3735.43,1467.83 3760.43,1467.83 3760.43,1447.83 3754.12,1443.1 3752.84,1443.08 3752.84,1443.07 3751.7,1443.01 3750.58,1442.84 3749.47,1442.58 3748.38,1442.22 3747.33,1441.77 3746.33,1441.23 3745.38,1440.6 3744.48,1439.89 3743.65,1439.11 3742.89,1438.26 3742.21,1437.34 3741.61,1436.37 3741.1,1435.35 3741.03,1435.2 3740,1432.83 3700.43,1432.83 3650.43,1387.83 3586.19,1387.83 3586.19,1432.83 3620.43,1432.83 3622.77,1434.13 3624.8,1432.64 3624.81,1432.64 3625.81,1431.97 3626.86,1431.39 3627.97,1430.91 3629.11,1430.52 3630.28,1430.24 3631.47,1430.06 3632.67,1429.98 3633.87,1430.01 3635.07,1430.14 3636.25,1430.37 3637.4,1430.71 3638.52,1431.15 3639.6,1431.68 3640.63,1432.31 3641.6,1433.02 3642.51,1433.82 3643.34,1434.69 3644.09,1435.63 3644.76,1436.63 3645.34,1437.69 3645.82,1438.79 3646.21,1439.93 3646.49,1441.1 3646.67,1442.29 3646.75,1443.49 3646.72,1444.69 3646.71,1444.81 3646.52,1447.33
LDO2 on Bottom Layer "BOTTOM-LDO2" (solid, pour order 236): 263 vertices, not listed, extent 3475.47,1453.62 3715.43,1512.68
LDOUSB on Bottom Layer "BOTTOM-LDOUSB" (solid, pour order 234): 3540,1675 3599.48,1674.09 3609.32,1683.93 3632.95,1683.93 3697.91,1618.97 3697.91,1600.35 3708.53,1589.73 3708.46,1588.01 3708.47,1586.86 3708.57,1585.73 3708.77,1584.61 3709.07,1583.5 3709.47,1582.43 3709.95,1581.4 3710.53,1580.42 3711.19,1579.48 3711.92,1578.61 3712.73,1577.81 3713.61,1577.08 3715.43,1575.74 3715.43,1562.83 3690.43,1562.83 3651.55,1600.91 3651.55,1612.24 3651.78,1613.77 3651.83,1614.97 3651.78,1616.18 3651.63,1617.37 3651.55,1623.95 3648.53,1623.95 3647.71,1624.82 3646.82,1625.63 3645.86,1626.36 3644.84,1627 3643.76,1627.54 3642.65,1628 3641.5,1628.35 3640.32,1628.6 3639.13,1628.75 3637.92,1628.8 3636.72,1628.73 3635.53,1628.57 3634.35,1628.3 3633.21,1627.93 3632.1,1627.46 3631.12,1626.98 3626.27,1626.98 3582.53,1627.07 3565.25,1626.85 3540,1630
3V3 on Bottom Layer "BOTTOM-VSYS 2" (solid, pour order 245): 3781.39,1607.83 3779.47,1609.75 3775.43,1617.83 3775.43,1712.83 3765.43,1727.83 3765.43,1787.83 3955.43,1787.83 3955.43,1732.83 3940.43,1707.83 3940.43,1607.83 3781.39,1607.83
3V3 on Bottom Layer "BOTTOM-VSYS 1" (solid, pour order 243): 4025.43,1592.83 4040.43,1592.83 4110.43,1627.83 4170.43,1627.83 4170.43,1457.83 4110.43,1457.83 4105.43,1452.83 4025.43,1452.83 4025.43,1592.83
3V3 on Bottom Layer "BOTTOM-VSYS" (solid, pour order 246): 3970.43,1197.83 3775.43,1197.83 3775.43,1377.83 3925.43,1377.83 3950.43,1372.83 3950.43,1287.83 3970.43,1257.83 3970.43,1197.83
LDO3 on Bottom Layer "BOTTOM-LDO3" (solid, pour order 242): 4025.16,1656.68 4003.89,1631.86 4003.15,1631.76 4002.05,1631.55 4000.96,1631.24 3999.91,1630.84 3998.89,1630.35 3997.92,1629.78 3997.01,1629.12 3996.15,1628.39 3995.36,1627.58 3994.65,1626.71 3994.01,1625.78 3993.46,1624.79 3993,1623.77 3992.63,1622.7 3992.35,1621.61 3992.16,1620.5 3992.08,1619.37 3992.08,1618.58 3992.1,1617.83 3977.17,1599.92 3976.02,1600.15 3974.91,1600.32 3973.78,1600.39 3972.84,1600.41 3964.87,1608.34 3964.87,1634.31 3968.22,1638.6 3969.53,1638.17 3970.62,1637.87 3971.73,1637.67 3972.85,1637.56 3973.98,1637.55 3975.1,1637.65 3976.21,1637.83 3977.31,1638.12 3978.3,1638.47 3964.87,1629.81 3964.87,1654.92 3964.87,1670.04 3964.87,1675.13 4180.43,1892.83 4210.43,1892.83 4210.43,1852.83 4190.43,1852.83 4039.3,1694.62 4037.18,1694.87 4036.06,1694.88 4034.93,1694.79 4033.82,1694.61 4032.73,1694.32 4031.67,1693.95 4030.64,1693.48 4029.66,1692.93 4028.73,1692.29 4027.86,1691.58 4027.05,1690.79 4026.32,1689.93 4025.66,1689.01 4025.09,1688.04 4024.61,1687.03 4024.21,1685.97 4023.91,1684.88 4023.7,1683.78 4023.59,1682.65 4023.58,1681.53 4023.67,1680.4 4023.85,1679.29 4024.13,1678.2 4024.51,1677.14 4024.98,1676.11 4025.53,1675.13 4026.17,1674.2 4026.88,1673.33 4027.67,1672.53 4028.53,1671.79 4029.45,1671.14 4030.42,1670.56 4030.43,1662.83 4028.62,1660.72 4027.62,1659.86 4026.84,1659.05 4026.12,1658.18 4025.49,1657.24
SMPS9 on Bottom Layer "BOTTOM-SMPS9" (solid, pour order 239): 4395.43,1472.83 4395.43,1577.83 4515.43,1577.83 4515.43,1472.83 4395.43,1472.83
SMPS6 on Bottom Layer "BOTTOM-SMPS6" (solid, pour order 235): 4435.43,1272.83 4350.43,1272.83 4350.43,1377.83 4435.13,1377.83 4435.43,1377.53 4435.43,1272.83
SMPS7 on Bottom Layer "BOTTOM-N46924472" (solid, pour order 231): 3625.43,977.83 3620.43,972.83 3620.43,922.83 3740.43,922.83 3740.43,972.83 3735.43,977.83 3625.43,977.83
SMPS3 on Bottom Layer "BOTTOM-N46921072" (solid, pour order 237): 3995,2020 3995,2045 3985,2055 3985,2105 4105,2105 4105,2020 3995,2020
LDOLN on Bottom Layer "BOTTOM-LDOLN" (solid, pour order 233): 3709.76,1372.34 3630.43,1292.83 3565,1295 3565,1330 3600.43,1332.83 3655.43,1382.83 3700.43,1422.83 3715.43,1422.83 3715.43,1409.89 3714.46,1409.31 3713.55,1408.65 3712.69,1407.92 3711.91,1407.11 3711.19,1406.24 3710.56,1405.31 3710,1404.33 3709.54,1403.3 3709.17,1402.24 3708.89,1401.14 3708.71,1400.03 3708.62,1398.91 3708.63,1397.78 3708.74,1396.66 3708.95,1395.55 3709.26,1394.47 3709.66,1393.41 3710.14,1392.4 3710.72,1391.43 3711.38,1390.51 3712.11,1389.66 3712.92,1388.87 3713.79,1388.15 3714.72,1387.52 3715.43,1387.11 3715.43,1378.4 3714.46,1377.82 3713.55,1377.16 3712.69,1376.43 3711.91,1375.62 3711.19,1374.75 3710.56,1373.82 3710,1372.84
LDO2 on Bottom Layer "TOP-LDO2" (solid, pour order 228): 3455,1510 3505,1510 3505,1470 3455,1470 3455,1510
GND on Top Layer "Top Layer-No Net" (solid, remove dead copper, pour order 216): 50,2950 4950,2950 4950,50 50,50
GND on Top Layer "TOP-GND 11" (solid, pour order 202): 4056.34,1656.44 4042.08,1642.83 4030.43,1642.83 4030.43,1712.83 4065,1750 4065,1805 4090,1805 4125.43,1805 4125.43,1722.37 4062.58,1662.39 4062.06,1662.13 4061.07,1661.57 4060.13,1660.92 4059.25,1660.19 4058.44,1659.39 4057.69,1658.53 4057.03,1657.6 4056.63,1656.94
GND on Top Layer "TOP-GND" (solid, pour order 192): 3550.43,1437.83 3505.43,1437.83 3505.43,1472.83 3550.43,1472.83 3550.43,1437.83
NetL12_1 on Top Layer "TOP-SMPS9_SW" (solid, pour order 205): 4025.43,1507.83 4076.26,1507.83 4085.43,1515.69 4085.43,1557.83 4090.43,1562.83 4215.43,1562.83 4215.43,1477.83 4205.43,1467.83 4090.43,1467.83 4080.43,1477.83 4025.43,1477.83 4025.43,1507.83
NetL11_1 on Top Layer "TOP-SMPS8_SW" (solid, pour order 212): 4203.89,1625.41 4147.63,1572.83 4025.43,1572.83 4025.43,1602.83 4075.43,1602.83 4130.43,1657.83 4151.94,1750.84 4171.05,1767.83 4240.43,1767.83 4240.43,1659.56 4208.64,1629.85 4208.29,1629.64 4207.29,1628.97 4206.35,1628.22 4205.48,1627.38 4204.69,1626.48 4204.13,1625.75 4203.89,1625.41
